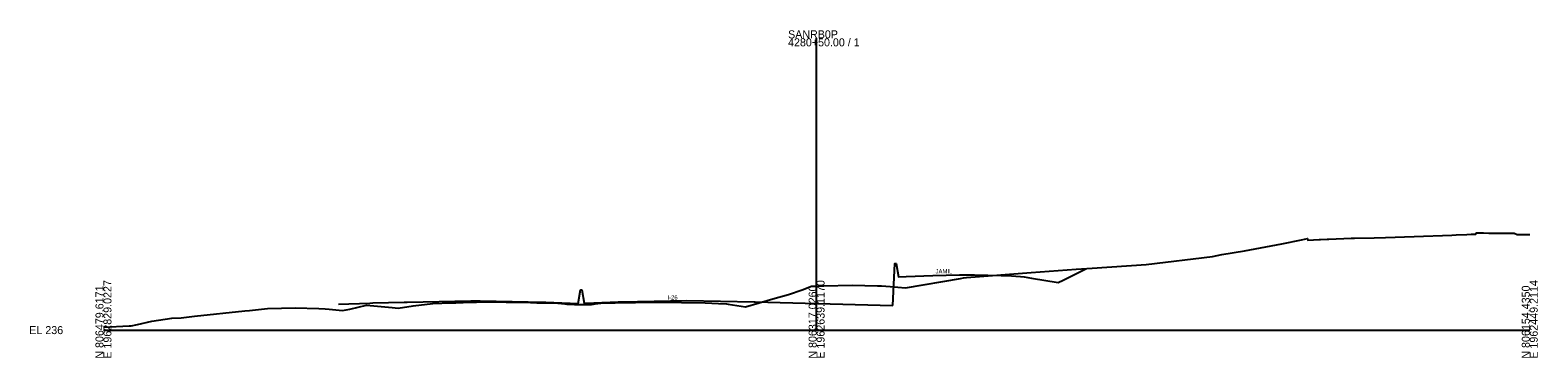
# Model space of a CAD drawing. Extents: x 1995641 to 1997170, y 790368 to 809963.
# Drawn here: x 1995641 to 1996170, y 791368 to 791483 of the extents above; entities that cross this region are included whole.
import ezdxf

# ---------------------------------------------------------------- set-up
doc = ezdxf.new("R2010")
doc.units = 0
for name, color, linetype in [('Default', 7, 'Continuous'), ('RD_GPK_XS_Cell', 7, 'Continuous'), ('RD_Sketch1', 7, 'Continuous'), ('RD_XS_ExGround', 7, 'Continuous'), ('RD_XS_Pave', 7, 'Continuous')]:
    doc.layers.add(name, color=color, linetype=linetype)

msp = doc.modelspace()

# ---------------------------------------------------------------- linework, layer by layer
at = {"layer": 'RD_GPK_XS_Cell'}
for p, q in [((1995917.06, 791378.11), (1995917.06, 791480.2)), ((1995667.06, 791378.11), (1995917.06, 791378.11)), ((1995917.06, 791378.11), (1996167.06, 791378.11))]:
    msp.add_line(p, q, dxfattribs=at)
at = {"layer": 'RD_XS_ExGround'}
msp.add_lwpolyline([(1995667.06, 791379.16), (1995676.12, 791379.61), (1995676.81, 791379.63), (1995678.99, 791380.02), (1995683.97, 791381.26), (1995691.05, 791382.31), (1995694.33, 791382.42), (1995698.92, 791382.94), (1995716.64, 791384.87), (1995718.25, 791385.01), (1995724.55, 791385.68), (1995729.43, 791385.83), (1995734.29, 791385.93), (1995742.57, 791385.69), (1995744.79, 791385.61), (1995746.18, 791385.46), (1995750.91, 791384.95), (1995753.43, 791385.47), (1995759.29, 791386.78), (1995768.26, 791385.97), (1995770.38, 791385.79), (1995775.67, 791386.55), (1995782.5, 791387.45), (1995789, 791387.63), (1995790.62, 791387.67), (1995793.15, 791387.75), (1995802.58, 791388.02), (1995808.22, 791387.93), (1995814.38, 791387.83), (1995819, 791387.7), (1995826.34, 791387.5), (1995828.85, 791387.34), (1995829.55, 791387.17), (1995832.15, 791387.05), (1995834.13, 791387.03), (1995835.12, 791387.01), (1995837.14, 791387.09), (1995838.05, 791387.12), (1995838.29, 791387.21), (1995838.72, 791387.23), (1995838.99, 791387.32), (1995839.4, 791387.35), (1995841.39, 791387.49), (1995851.52, 791387.76), (1995853.57, 791387.82), (1995857.38, 791387.84), (1995865.47, 791387.91), (1995869.71, 791387.79), (1995877.96, 791387.6), (1995882.71, 791387.41), (1995885.46, 791387.31), (1995886.11, 791387.21), (1995892.1, 791386.2), (1995901.77, 791389.05), (1995907.23, 791390.56), (1995911.99, 791392.18), (1995915.27, 791393.44), (1995917.06, 791393.54), (1995918.28, 791393.61), (1995919, 791393.63), (1995919.61, 791393.64), (1995929.52, 791393.83), (1995938.35, 791393.65), (1995939.86, 791393.63), (1995942.83, 791393.37), (1995948.25, 791392.92), (1995967.54, 791396.19), (1995968.53, 791396.37), (1995969.65, 791396.46), (1995992.33, 791398.3), (1996008.04, 791399.39), (1996013.61, 791399.77), (1996032.55, 791401.03), (1996055.83, 791403.82), (1996059.16, 791404.52), (1996067.08, 791405.88), (1996080.13, 791408.25), (1996087.03, 791409.74), (1996089.17, 791410.12), (1996089.29, 791409.62), (1996093.27, 791409.78), (1996093.69, 791409.8), (1996096.01, 791409.89), (1996096.68, 791409.92), (1996104.46, 791410.24), (1996105.62, 791410.28), (1996112.57, 791410.39), (1996116.45, 791410.49), (1996126.52, 791410.81), (1996139.8, 791411.37), (1996141.24, 791411.43), (1996145, 791411.56), (1996146.57, 791411.62), (1996148.11, 791411.65), (1996148.25, 791412.14), (1996148.85, 791412.12), (1996149.58, 791412.1), (1996150.9, 791412.09), (1996152.71, 791412.08), (1996161.63, 791412.05), (1996162.59, 791411.56), (1996167.06, 791411.53)], dxfattribs=at)
at = {"layer": 'RD_XS_Pave'}
for points in [[(1995943.73, 791386.77), (1995944.49, 791401.43), (1995944.99, 791401.43), (1995945.74, 791396.76), (1995948.48, 791396.87), (1995957.78, 791397.24), (1995967.2, 791397.43), (1995969.78, 791397.48), (1995972.39, 791397.43), (1995981.78, 791397.24), (1995982.22, 791397.24), (1995983.78, 791397.21), (1995988.48, 791396.83), (1995989.78, 791396.73), (1995992.4, 791396.29), (1996001.78, 791394.73), (1996003.53, 791395.6), (1996011.4, 791399.54)], [(1995749.5, 791387.15), (1995760.45, 791387.58), (1995761.5, 791387.62), (1995772.53, 791387.89), (1995773.51, 791387.92), (1995795.87, 791388.35), (1995797.52, 791388.38), (1995799.13, 791388.35), (1995821.53, 791387.89), (1995822.18, 791387.86), (1995833.53, 791387.4), (1995834.28, 791392.22), (1995834.78, 791392.22), (1995835.53, 791387.54), (1995836.09, 791387.57), (1995847.54, 791388.02), (1995848.5, 791388.04), (1995871.55, 791388.49), (1995895.21, 791388), (1995895.55, 791387.99), (1995943.73, 791386.77)]]:
    msp.add_lwpolyline(points, dxfattribs=at)

# ---------------------------------------------------------------- texts
at = {"layer": 'Default'}
msp.add_text('-', height=0.0001, dxfattribs=at).set_placement((1995667.06, 791378.11))
msp.add_text('-', height=0.0001, dxfattribs=at).set_placement((1995667.06, 791378.11))
at = {"layer": 'RD_GPK_XS_Cell'}
for s, p in [('SANRB0P', (1995907.06, 791480.2)), ('4280+50.00 / 1', (1995907.06, 791477.4)), ('EL 236', (1995641.06, 791376.71))]:
    msp.add_text(s, height=2.8, dxfattribs=at).set_placement(p)
for s, p in [('N 806479.6171', (1995667.06, 791368.11)), ('E 1962829.0227', (1995669.86, 791368.11)), ('N 806317.0260', (1995917.06, 791368.11)), ('E 1962639.1170', (1995919.86, 791368.11)), ('N 806154.4350', (1996167.06, 791368.11)), ('E 1962449.2114', (1996169.86, 791368.11))]:
    msp.add_text(s, height=2.8, rotation=90, dxfattribs=at).set_placement(p)
at = {"layer": 'RD_Sketch1'}
msp.add_text('251.43', height=0.1, dxfattribs=at).set_placement((1995916.85, 791393.44))
at = {"layer": 'RD_XS_Pave'}
for s, p in [('JAMIL', (1995958.77, 791397.94)), ('I-26', (1995864.78, 791388.78))]:
    msp.add_text(s, height=1.5, dxfattribs=at).set_placement(p)

doc.saveas('drawing.dxf')
